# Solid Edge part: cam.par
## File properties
Author: Deepak Maini
Template: normal.par
Last saved by: Robert a Rhodes jr
Revision: 2
Application: Solid Edge
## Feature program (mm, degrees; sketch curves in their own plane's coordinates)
sketch for "unnamed Protrusion 1" plane through (0, 0, 0) normal (0, -1, 0) x-axis (1, 0, 0)
  line (-48.7213, 38.3333) -> (-48.7213, 0)
  line (-48.7213, 0) -> (73.8435, 0)
  line (73.8435, 0) -> (73.8435, -9.0712)
  line (73.8435, -9.0712) -> (-55.4516, -9.0712)
  line (-55.4516, -9.0712) -> (-55.4516, 38.3333)
  line (-55.4516, 38.3333) -> (-48.7213, 38.3333)
extrude "unnamed Protrusion 1" add finite 37.8 along -normal
sketch for "unnamed Cutout 1" plane through (-48.7213, 18.9, 19.1666) normal (1, 0, 0) x-axis (0, 1, 0)
  line (-5.0674, -0.2952) -> (-5.0674, 8.2652)
  line (-5.0674, 8.2652) -> (3.6898, 8.2652)
  line (3.6898, 8.2652) -> (3.6898, -0.2952)
  line (3.6898, -0.2952) -> (-5.0674, -0.2952)
extrude "unnamed Cutout 1" cut finite 123.95 along -normal
sketch for "unnamed Hole 1" plane through (12.5611, 18.9, 0) normal (0, 0, 1) x-axis (0, 1, 0)
  hole centre (0.7865, -41.5278) bore radius 3.5
hole "unnamed Hole 1" through
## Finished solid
Body 1: solid body, 13 faces, 32 edges, 20 vertices.
  Faces by surface: plane 12, cylinder 1
  Edges by curve: line 30, circle 2
Bounding box of the edges (mm): 129.295 x 37.800 x 47.404, from (-55.4516, 0, -9.0712) to (73.8435, 37.8, 38.3333).
Cylindrical faces by radius (mm): R3.5 x1
Planar faces by outward normal: +x 2, +y 2, +z 3, -x 1, -y 2, -z 2
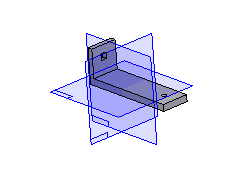
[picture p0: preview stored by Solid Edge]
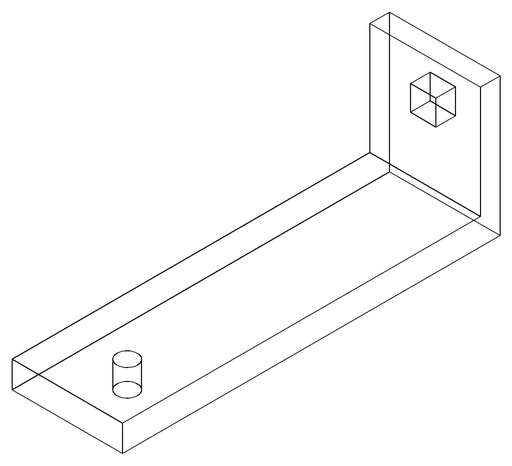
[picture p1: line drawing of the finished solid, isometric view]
